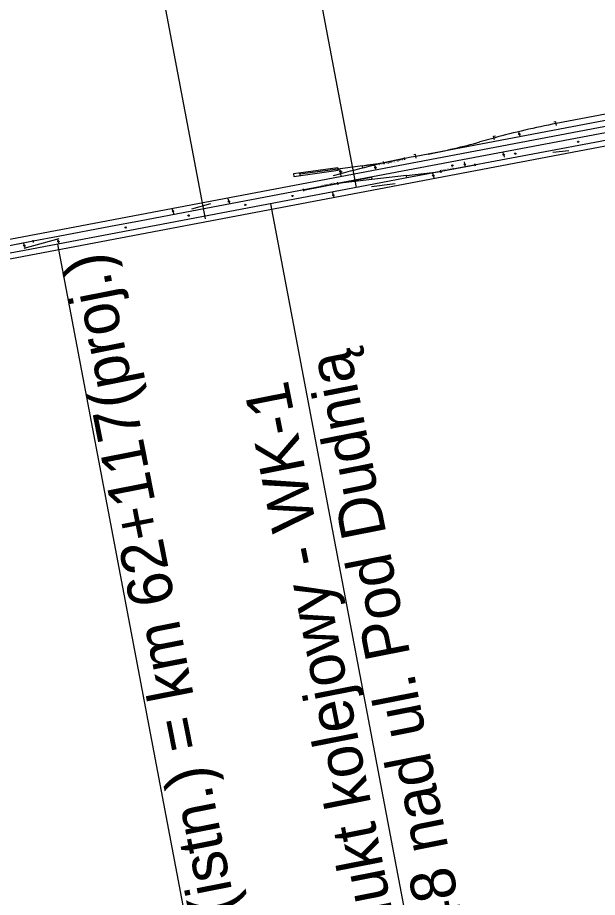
# Model space of a CAD drawing. Extents: x 6540402 to 6566579, y 5525343 to 5532423.
# Drawn here: x 6556959 to 6557412, y 5528082 to 5528769 of the extents above; entities that cross this region are included whole.
import ezdxf

# ---------------------------------------------------------------- set-up
doc = ezdxf.new("R2010")
doc.units = 0
for name, color, linetype in [('T_plan_koziol oporowy', 7, 'Continuous'), ('TOR_PS_ODW-studnie betonowe', 7, 'Continuous'), ('TOR_PS_OPIS_T-hektometry projektowane', 7, 'Continuous'), ('TOR_PS_OPIS_T-opisy dodatkowe', 7, 'Continuous'), ('TOR_PS_OPIS_T-symbole geometrii', 7, 'Continuous'), ('TOR_PS_OPIS_T-ukresy', 7, 'Continuous'), ('TOR_PS_T-rozjazdy projektowane', 7, 'Continuous'), ('TOR_PS_T-tory projektowane', 7, 'Continuous')]:
    doc.layers.add(name, color=color, linetype=linetype)

msp = doc.modelspace()

# ---------------------------------------------------------------- linework, layer by layer
at = {"layer": 'T_plan_koziol oporowy'}
for p, q in [((6557209.03, 5528650.47), (6557179.31, 5528646.42)), ((6557208.9, 5528651.46), (6557209.17, 5528649.48)), ((6557179.17, 5528647.41), (6557179.87, 5528647.51)), ((6557179.44, 5528645.43), (6557179.17, 5528647.41)), ((6557179.44, 5528645.43), (6557180.14, 5528645.52))]:
    msp.add_line(p, q, dxfattribs=at)
msp.add_lwpolyline([(6557174.49, 5528644.76), (6557209.17, 5528649.48), (6557208.9, 5528651.46), (6557174.22, 5528646.71)], close=True, dxfattribs=at)
at = {"layer": 'TOR_PS_ODW-studnie betonowe'}
for centre, radius in [((6557396.67, 5528671.79), 0.5), ((6557396.67, 5528671.79), 0.25), ((6557347.55, 5528662.48), 0.5), ((6557347.55, 5528662.48), 0.25), ((6557298.42, 5528653.17), 0.5), ((6557298.42, 5528653.17), 0.25), ((6557173.54, 5528629.43), 0.5), ((6557173.54, 5528629.43), 0.25), ((6557136.62, 5528622.5), 0.5), ((6557136.62, 5528622.5), 0.25), ((6557092.41, 5528614.11), 0.5), ((6557092.41, 5528614.11), 0.25), ((6557043.28, 5528604.8), 0.5), ((6557043.28, 5528604.8), 0.25)]:
    msp.add_circle(centre, radius, dxfattribs=at)
at = {"layer": 'TOR_PS_OPIS_T-hektometry projektowane'}
msp.add_lwpolyline([(6557105.67, 5528611.67), (6556963.2, 5529363.28)], dxfattribs=at)
at = {"layer": 'TOR_PS_OPIS_T-opisy dodatkowe'}
for p, q in [((6557079.83, 5529392.34), (6557223.2, 5528635.96)), ((6557156.39, 5528623.29), (6557299.77, 5527866.91)), ((6557133.72, 5527835.44), (6556990.35, 5528591.82))]:
    msp.add_line(p, q, dxfattribs=at)
at = {"layer": 'TOR_PS_OPIS_T-symbole geometrii'}
for p, q in [((6557379.23, 5528687.46), (6557377.75, 5528687.18)), ((6557379.79, 5528684.52), (6557379.23, 5528687.46)), ((6557330.54, 5528676.12), (6557331.98, 5528676.52)), ((6557331.34, 5528673.23), (6557330.54, 5528676.12)), ((6557269.68, 5528661.86), (6557268.2, 5528661.59)), ((6557270.24, 5528658.92), (6557269.68, 5528661.86)), ((6557210.87, 5528648.16), (6557212.31, 5528648.56)), ((6557211.67, 5528645.27), (6557210.87, 5528648.16))]:
    msp.add_line(p, q, dxfattribs=at)
at = {"layer": 'TOR_PS_OPIS_T-ukresy'}
for p, q in [((6557350.68, 5528678.24), (6557350.33, 5528679.7)), ((6557350.89, 5528677.26), (6557351.17, 5528675.79)), ((6557338.44, 5528662.18), (6557338.16, 5528663.65)), ((6557308.07, 5528654.59), (6557307.89, 5528656.08)), ((6557338.6, 5528661.19), (6557338.77, 5528659.69)), ((6557210.84, 5528649.2), (6557210.63, 5528650.68)), ((6557238.16, 5528652.07), (6557237.81, 5528653.54)), ((6557238.37, 5528651.09), (6557238.65, 5528649.62)), ((6557308.22, 5528653.6), (6557308.5, 5528652.12)), ((6557211.04, 5528648.22), (6557211.44, 5528646.76)), ((6557283.39, 5528645.84), (6557283.11, 5528647.31)), ((6557283.56, 5528644.85), (6557283.86, 5528642.98)), ((6557205.34, 5528630.53), (6557205.03, 5528632.51)), ((6557205.52, 5528629.55), (6557205.8, 5528628.08)), ((6557123.77, 5528625.55), (6557123.36, 5528627.22)), ((6557123.98, 5528624.58), (6557124.26, 5528623.1)), ((6557080.05, 5528618.03), (6557079.77, 5528619.5)), ((6557080.27, 5528617.05), (6557080.68, 5528615.39)), ((6556990.56, 5528594.4), (6556990.16, 5528595.86)), ((6556990.79, 5528593.43), (6556991.07, 5528591.95)), ((6556963.93, 5528591.19), (6556963.65, 5528592.66)), ((6556964.15, 5528590.21), (6556964.56, 5528588.76))]:
    msp.add_line(p, q, dxfattribs=at)
for centre in [(6557350.8, 5528677.75), (6557338.54, 5528661.69), (6557210.9, 5528648.7), (6557238.27, 5528651.58), (6557308.13, 5528654.09), (6557283.49, 5528645.35), (6557205.42, 5528630.04), (6557123.89, 5528625.07), (6557080.15, 5528617.54), (6556990.69, 5528593.92), (6556964.02, 5528590.69)]:
    msp.add_circle(centre, 0.5, dxfattribs=at)
at = {"layer": 'TOR_PS_T-rozjazdy projektowane'}
for p, q in [((6557244.38, 5528656.31), (6557244.77, 5528654.35)), ((6557260.67, 5528659.59), (6557261.06, 5528657.63)), ((6557289.74, 5528647.55), (6557289.37, 5528649.52)), ((6557316.19, 5528653.58), (6557289.56, 5528648.53)), ((6557316.38, 5528652.6), (6557316, 5528654.56)), ((6557181.88, 5528635.04), (6557182.25, 5528633.08)), ((6557182.06, 5528634.06), (6557208.7, 5528639.11)), ((6557208.51, 5528640.09), (6557208.88, 5528638.13)), ((6556971.05, 5528594.06), (6556944.41, 5528589.01)), ((6556971.23, 5528593.08), (6556970.86, 5528595.04))]:
    msp.add_line(p, q, dxfattribs=at)
for points in [[(6557228.11, 5528653.06), (6557244.57, 5528655.33), (6557260.86, 5528658.61), (6557244.57, 5528655.33), (6557228.46, 5528651.26)], [(6557289.56, 5528648.53), (6557262.92, 5528643.48), (6557262.63, 5528645.4)], [(6557289.56, 5528648.53), (6557262.92, 5528643.48), (6557262.63, 5528645.4)], [(6557208.7, 5528639.11), (6557235.33, 5528644.16), (6557235.62, 5528642.25)], [(6557208.7, 5528639.11), (6557235.33, 5528644.16), (6557235.62, 5528642.25)]]:
    msp.add_lwpolyline(points, close=True, dxfattribs=at)
at = {"layer": 'TOR_PS_T-tory projektowane'}
for p, q in [((6558571.55, 5528891.54), (6557352.88, 5528660.54)), ((6557652.06, 5528732.82), (6557269.96, 5528660.39)), ((6557651.07, 5528737.47), (6557379.51, 5528685.99)), ((6557664.82, 5528730.4), (6555967.41, 5528408.66)), ((6557665.78, 5528725.75), (6557203.03, 5528638.04)), ((6557450.25, 5528674.41), (6556612.98, 5528515.71)), ((6557330.94, 5528674.67), (6557319.91, 5528671.62)), ((6557389.48, 5528664.65), (6557376.96, 5528663.34)), ((6557352.88, 5528660.54), (6557289.2, 5528648.47)), ((6557228.1, 5528653.06), (6557209.03, 5528650.47)), ((6557289.2, 5528648.47), (6557272.49, 5528645.3)), ((6557211.27, 5528646.72), (6557205.25, 5528645.05)), ((6557272.49, 5528645.3), (6557231.63, 5528637.55)), ((6557262.63, 5528645.4), (6557235.62, 5528642.25)), ((6557231.63, 5528637.55), (6556964.14, 5528586.85)), ((6557203.03, 5528638.04), (6557162.17, 5528630.29)), ((6557253.65, 5528638.93), (6557235.26, 5528636.46)), ((6557162.17, 5528630.29), (6557094.92, 5528617.54)), ((6557109.57, 5528623.4), (6557094.53, 5528619.23)), ((6557094.92, 5528617.54), (6557054.06, 5528609.8)), ((6557054.06, 5528609.8), (6557031.44, 5528605.51)), ((6557031.44, 5528605.51), (6556990.57, 5528597.76)), ((6556971.05, 5528594.06), (6556930.18, 5528586.32)), ((6556990.97, 5528596.08), (6556963.75, 5528588.53)), ((6556990.57, 5528597.76), (6556971.05, 5528594.06)), ((6556964.14, 5528586.85), (6556923.27, 5528579.1))]:
    msp.add_line(p, q, dxfattribs=at)
for centre, radius, start, end in [((6557491.25, 5528096.49), 600, 100.73324, 105.49688), ((6557186.32, 5529153.44), 500, 280.73324, 285.49688), ((6557404.98, 5527948.07), 725, 100.73325, 105.4969), ((6557159, 5529160.79), 512.41, 277.75012, 281.46575)]:
    msp.add_arc(centre, radius, start, end, dxfattribs=at)

# ---------------------------------------------------------------- texts
at = {"layer": 'TOR_PS_OPIS_T-opisy dodatkowe'}
for s, p in [('km 62+117(istn.) = km 62+117(proj.)', (6557174.57, 5527843.15)), ('km 61+948 nad ul. Pod Dudnią', (6557342.99, 5527879.08)), ('Proj. Wiadukt kolejowy - WK-1', (6557291.49, 5527868.92))]:
    msp.add_text(s, height=35, rotation=101.15785, dxfattribs=at).set_placement(p)
at = {"layer": 'TOR_PS_T-rozjazdy projektowane'}
for s, rotation, p in [('Rłd-60E1-725,000/512,414-1:9', 191.36081, (6557259.85, 5528658.05)), ('Rz-60E1-760-1:14', 190.73324, (6557299.52, 5528651.72)), ('Rz-60E1-760-1:14', 190.73324, (6557206.63, 5528640.01))]:
    msp.add_text(s, height=1, rotation=rotation, dxfattribs=at).set_placement(p)

doc.saveas('drawing.dxf')
